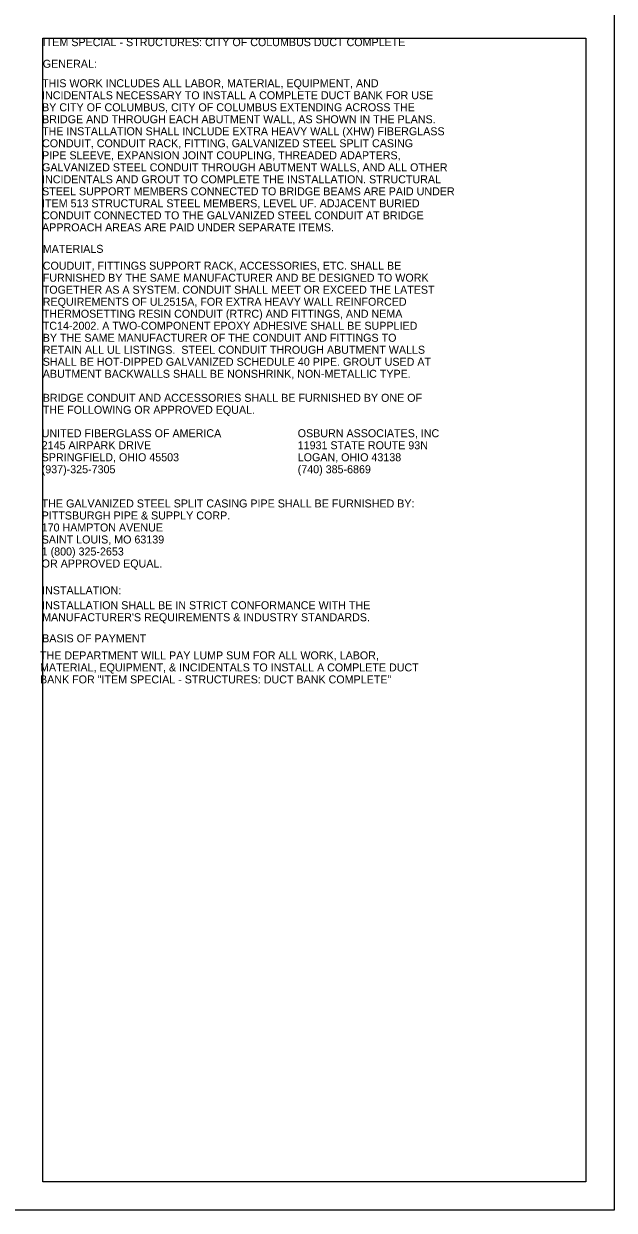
# Model space of a CAD drawing. Extents: x -27.4 to 41.5, y -43.2 to 24.4.
# Drawn here: x 21.41 to 31.74, y -22.74 to -1.99 of the extents above; entities that cross this region are included whole.
import ezdxf

# ---------------------------------------------------------------- set-up
doc = ezdxf.new("R2010")
doc.units = 0
for name, color, linetype in [('BR_P_Slab_Object', 7, 'Continuous'), ('BR_P_Sub_Foot_Hidden', 7, 'Continuous'), ('SH_Data', 7, 'Continuous')]:
    doc.layers.add(name, color=color, linetype=linetype)

msp = doc.modelspace()

# ---------------------------------------------------------------- linework, layer by layer
at = {"layer": 'BR_P_Slab_Object'}
msp.add_lwpolyline([(21.744, -2.241), (31.244, -2.241), (31.244, -22.241), (21.744, -22.241)], close=True, dxfattribs=at)
at = {"layer": 'SH_Data'}
msp.add_lwpolyline([(1.244, -1.741), (31.744, -1.741), (31.744, -22.741), (1.244, -22.741)], close=True, dxfattribs=at)

# ---------------------------------------------------------------- texts
at = {"layer": 'BR_P_Sub_Foot_Hidden'}
for s, p in [('ITEM SPECIAL - STRUCTURES: CITY OF COLUMBUS DUCT COMPLETE', (21.744, -2.382)), ('GENERAL:', (21.744, -2.76)), ('THIS WORK INCLUDES ALL LABOR, MATERIAL, EQUIPMENT, AND ', (21.732, -3.101)), ('INCIDENTALS NECESSARY TO INSTALL A COMPLETE DUCT BANK FOR USE ', (21.732, -3.311)), ('BY CITY OF COLUMBUS, CITY OF COLUMBUS EXTENDING ACROSS THE ', (21.732, -3.521)), ('BRIDGE AND THROUGH EACH ABUTMENT WALL, AS SHOWN IN THE PLANS. ', (21.732, -3.731)), ('THE INSTALLATION SHALL INCLUDE EXTRA HEAVY WALL (XHW) FIBERGLASS ', (21.732, -3.941)), ('CONDUIT, CONDUIT RACK, FITTING, GALVANIZED STEEL SPLIT CASING ', (21.732, -4.151)), ('PIPE SLEEVE, EXPANSION JOINT COUPLING, THREADED ADAPTERS, ', (21.732, -4.361)), ('GALVANIZED STEEL CONDUIT THROUGH ABUTMENT WALLS, AND ALL OTHER ', (21.732, -4.571)), ('INCIDENTALS AND GROUT TO COMPLETE THE INSTALLATION. STRUCTURAL ', (21.732, -4.781)), ('STEEL SUPPORT MEMBERS CONNECTED TO BRIDGE BEAMS ARE PAID UNDER ', (21.732, -4.991)), ('ITEM 513 STRUCTURAL STEEL MEMBERS, LEVEL UF. ADJACENT BURIED ', (21.732, -5.201)), ('CONDUIT CONNECTED TO THE GALVANIZED STEEL CONDUIT AT BRIDGE ', (21.732, -5.411)), ('APPROACH AREAS ARE PAID UNDER SEPARATE ITEMS.', (21.732, -5.621)), ('MATERIALS', (21.744, -5.997)), ('COUDUIT, FITTINGS SUPPORT RACK, ACCESSORIES, ETC. SHALL BE ', (21.744, -6.292)), ('FURNISHED BY THE SAME MANUFACTURER AND BE DESIGNED TO WORK ', (21.744, -6.502)), ('TOGETHER AS A SYSTEM. CONDUIT SHALL MEET OR EXCEED THE LATEST ', (21.744, -6.712)), ('REQUIREMENTS OF UL2515A, FOR EXTRA HEAVY WALL REINFORCED ', (21.744, -6.922)), ('THERMOSETTING RESIN CONDUIT (RTRC) AND FITTINGS, AND NEMA ', (21.744, -7.132)), ('TC14-2002. A TWO-COMPONENT EPOXY ADHESIVE SHALL BE SUPPLIED ', (21.744, -7.342)), ('BY THE SAME MANUFACTURER OF THE CONDUIT AND FITTINGS TO ', (21.744, -7.552)), ('RETAIN ALL UL LISTINGS.  STEEL CONDUIT THROUGH ABUTMENT WALLS ', (21.744, -7.762)), ('SHALL BE HOT-DIPPED GALVANIZED SCHEDULE 40 PIPE. GROUT USED AT ', (21.744, -7.972)), ('ABUTMENT BACKWALLS SHALL BE NONSHRINK, NON-METALLIC TYPE.', (21.744, -8.182)), ('BRIDGE CONDUIT AND ACCESSORIES SHALL BE FURNISHED BY ONE OF ', (21.744, -8.602)), ('THE FOLLOWING OR APPROVED EQUAL.', (21.744, -8.812)), ('UNITED FIBERGLASS OF AMERICA', (21.725, -9.222)), ('OSBURN ASSOCIATES, INC', (26.205, -9.222)), ('2145 AIRPARK DRIVE', (21.725, -9.432)), ('11931 STATE ROUTE 93N', (26.205, -9.432)), ('SPRINGFIELD, OHIO 45503', (21.725, -9.642)), ('LOGAN, OHIO 43138', (26.205, -9.642)), ('(937)-325-7305', (21.725, -9.852)), ('(740) 385-6869', (26.205, -9.852)), ('THE GALVANIZED STEEL SPLIT CASING PIPE SHALL BE FURNISHED BY:', (21.725, -10.45)), ('PITTSBURGH PIPE & SUPPLY CORP.', (21.725, -10.66)), ('170 HAMPTON AVENUE', (21.725, -10.87)), ('SAINT LOUIS, MO 63139', (21.725, -11.08)), ('1 (800) 325-2653', (21.725, -11.29)), ('OR APPROVED EQUAL.', (21.725, -11.5)), ('INSTALLATION:', (21.733, -11.969)), ('INSTALLATION SHALL BE IN STRICT CONFORMANCE WITH THE ', (21.733, -12.23)), ("MANUFACTURER'S REQUIREMENTS & INDUSTRY STANDARDS.", (21.733, -12.44)), ('BASIS OF PAYMENT', (21.733, -12.809)), ('THE DEPARTMENT WILL PAY LUMP SUM FOR ALL WORK, LABOR, ', (21.696, -13.107)), ('MATERIAL, EQUIPMENT, & INCIDENTALS TO INSTALL A COMPLETE DUCT ', (21.696, -13.317)), ('BANK FOR "ITEM SPECIAL - STRUCTURES: DUCT BANK COMPLETE"', (21.696, -13.527))]:
    msp.add_text(s, height=0.14, dxfattribs=at).set_placement(p)

doc.saveas('drawing.dxf')
